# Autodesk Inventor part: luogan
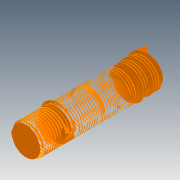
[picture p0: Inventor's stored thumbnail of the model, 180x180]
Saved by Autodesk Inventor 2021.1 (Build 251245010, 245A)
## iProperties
Created: 2021-05
Part Number: luogan
Material: Ogólny
Document SubType Name: Modeling
Designer: user
Density: 1 g/cm^3
Appearance: Domyślna
Author: user
Revision Number: ÈÎºÎ
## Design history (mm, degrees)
feature "Złożony1"
body "Srf1"
